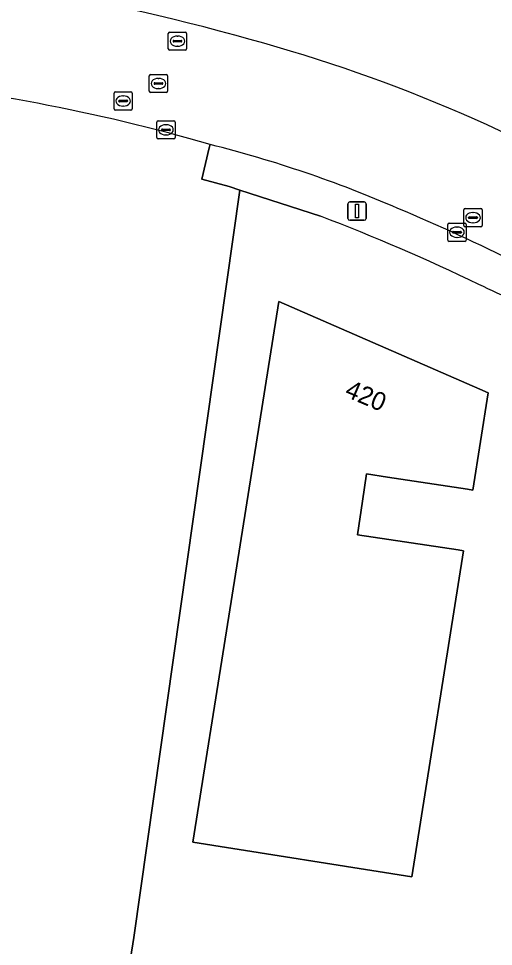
# Model space of a CAD drawing. Extents: x 154324 to 155744, y 382937 to 384188.
# Drawn here: x 155321.8 to 155347.8, y 383421.7 to 383472.5 of the extents above; entities that cross this region are included whole.
import ezdxf

# ---------------------------------------------------------------- set-up
doc = ezdxf.new("R2010")
doc.units = 0
for name, color, linetype in [('IMGEO_Erf', 7, 'Continuous'), ('IMGEO_Groenvoorziening', 7, 'Continuous'), ('IMGEO_Kolk', 7, 'Continuous'), ('IMGEO_Lichtmast', 7, 'Continuous'), ('IMGEO_Pand', 7, 'Continuous'), ('IMGEO_Pand_nummerreeks', 7, 'Continuous'), ('IMGEO_Rijbaan_lokaal_open', 7, 'Continuous'), ('IMGEO_Rioolput', 7, 'Continuous'), ('IMGEO_Voetpad_open', 7, 'Continuous')]:
    doc.layers.add(name, color=color, linetype=linetype)

msp = doc.modelspace()

# ---------------------------------------------------------------- linework, layer by layer
at = {"layer": 'IMGEO_Erf'}
msp.add_lwpolyline([(155338.312, 383461.713), (155333.894, 383463.145), (155328.096, 383422.22), (155326.654, 383413.134), (155323.037, 383390.342), (155343.85, 383387.039), (155363.801, 383383.796)], dxfattribs=at)
msp.add_lwpolyline([(155343.315, 383425.544), (155331.323, 383427.445), (155333.164, 383439.018), (155336.033, 383457.049), (155347.048, 383452.243), (155347.501, 383452.045), (155346.667, 383446.721), (155346.37, 383446.766), (155341.993, 383447.428), (155340.844, 383447.602), (155340.619, 383446.119), (155340.34, 383444.275), (155345.852, 383443.441), (155346.148, 383443.396)], close=True, dxfattribs=at)
for centre, radius, start, end in [((155299.548, 383359.815), 109.022, 64.20617, 69.17205), ((155325.371, 383410.082), 52.545, 60.8513, 65.7078)]:
    msp.add_arc(centre, radius, start, end, dxfattribs=at)
at = {"layer": 'IMGEO_Groenvoorziening'}
for points in [[(155333.894, 383463.145), (155333.316, 383463.332), (155331.811, 383463.731), (155332.222, 383465.445), (155332.268, 383465.636)], [(155241.462, 383401.286), (155286.115, 383394.2), (155322.727, 383388.39), (155323.037, 383390.342), (155326.654, 383413.134), (155328.096, 383422.22), (155333.894, 383463.145)]]:
    msp.add_lwpolyline(points, dxfattribs=at)
for centre, radius, start, end in [((155304.555, 383366.626), 108.94, 74.06499, 88.76862), ((155312.033, 383388.632), 85.735, 58.41362, 74.83277), ((155304.104, 383368.576), 101.064, 73.81877, 84.84587)]:
    msp.add_arc(centre, radius, start, end, dxfattribs=at)
at = {"layer": 'IMGEO_Kolk'}
for p, q in [((155329.353, 383466.014), (155329.353, 383466.866)), ((155329.428, 383466.94), (155330.28, 383466.94)), ((155330.354, 383466.866), (155330.354, 383466.014)), ((155329.612, 383466.434), (155329.612, 383466.446)), ((155330.05, 383466.397), (155329.652, 383466.397)), ((155329.655, 383466.483), (155330.053, 383466.483)), ((155329.841, 383466.72), (155329.866, 383466.72)), ((155330.096, 383466.446), (155330.096, 383466.434)), ((155330.28, 383465.94), (155329.428, 383465.94)), ((155329.864, 383466.16), (155329.839, 383466.16)), ((155345.293, 383460.408), (155345.293, 383461.26)), ((155345.368, 383461.334), (155346.22, 383461.334)), ((155346.294, 383461.26), (155346.294, 383460.408)), ((155345.552, 383460.828), (155345.552, 383460.84)), ((155345.99, 383460.791), (155345.592, 383460.791)), ((155345.595, 383460.877), (155345.993, 383460.877)), ((155345.781, 383461.114), (155345.806, 383461.114)), ((155346.036, 383460.84), (155346.036, 383460.828)), ((155346.22, 383460.334), (155345.368, 383460.334)), ((155345.804, 383460.554), (155345.779, 383460.554))]:
    msp.add_line(p, q, dxfattribs=at)
for points in [[(155329.353, 383466.014), (155329.353, 383466.866)], [(155329.428, 383466.94), (155330.28, 383466.94)], [(155330.354, 383466.866), (155330.354, 383466.014)], [(155330.28, 383465.94), (155329.428, 383465.94)], [(155345.293, 383460.408), (155345.293, 383461.26)], [(155345.368, 383461.334), (155346.22, 383461.334)], [(155346.294, 383461.26), (155346.294, 383460.408)], [(155346.22, 383460.334), (155345.368, 383460.334)]]:
    msp.add_lwpolyline(points, dxfattribs=at)
for centre, radius, start, end in [((155329.43, 383466.864), 0.0765, 91.552, 178.448), ((155329.43, 383466.864), 0.0765, 91.552, 178.448), ((155330.278, 383466.864), 0.0765, 1.552, 88.448), ((155330.278, 383466.864), 0.0765, 1.552, 88.448), ((155329.652, 383466.443), 0.0403, 85.8775, 175.7526), ((155329.649, 383466.433), 0.0366, 178.938, 274.7102), ((155330.053, 383466.44), 0.043, 264.8664, 352.4533), ((155330.057, 383466.445), 0.0386, 1.7309, 96.639), ((155329.43, 383466.016), 0.0765, 181.552, 268.448), ((155329.43, 383466.016), 0.0765, 181.552, 268.448), ((155330.278, 383466.016), 0.0765, 271.552, 358.448), ((155330.278, 383466.016), 0.0765, 271.552, 358.448), ((155345.37, 383461.258), 0.0765, 91.552, 178.448), ((155345.37, 383461.258), 0.0765, 91.552, 178.448), ((155346.218, 383461.258), 0.0765, 1.552, 88.448), ((155346.218, 383461.258), 0.0765, 1.552, 88.448), ((155345.592, 383460.837), 0.0403, 85.8775, 175.7526), ((155345.589, 383460.827), 0.0366, 178.938, 274.7102), ((155345.993, 383460.834), 0.043, 264.8664, 352.4533), ((155345.997, 383460.839), 0.0386, 1.7309, 96.639), ((155345.37, 383460.41), 0.0765, 181.552, 268.448), ((155345.37, 383460.41), 0.0765, 181.552, 268.448), ((155346.218, 383460.41), 0.0765, 271.552, 358.448), ((155346.218, 383460.41), 0.0765, 271.552, 358.448)]:
    msp.add_arc(centre, radius, start, end, dxfattribs=at)
for centre, major_axis, ratio, start_param, end_param in [((155329.84, 383466.44), (-0.387, 0.002), 0.722429, 4.712389, 7.853982), ((155329.865, 383466.44), (-0.39, 0.002), 0.717154, 1.570796, 4.712389), ((155345.78, 383460.834), (-0.387, 0.002), 0.722429, 4.712389, 7.853982), ((155345.805, 383460.834), (-0.39, 0.002), 0.717154, 1.570796, 4.712389)]:
    msp.add_ellipse(centre, major_axis=major_axis, ratio=ratio, start_param=start_param, end_param=end_param, dxfattribs=at)
at = {"layer": 'IMGEO_Lichtmast'}
for p, q in [((155339.824, 383461.59), (155339.824, 383462.39)), ((155339.824, 383462.39), (155339.824, 383461.59)), ((155339.924, 383462.49), (155340.714, 383462.49)), ((155340.714, 383462.49), (155339.924, 383462.49)), ((155340.814, 383462.39), (155340.814, 383461.59)), ((155340.814, 383461.59), (155340.814, 383462.39)), ((155340.714, 383461.49), (155339.924, 383461.49)), ((155339.924, 383461.49), (155340.714, 383461.49))]:
    msp.add_line(p, q, dxfattribs=at)
msp.add_lwpolyline([(155340.244, 383462.365), (155340.394, 383462.365), (155340.394, 383461.615), (155340.244, 383461.615), (155340.244, 383462.365)], dxfattribs=at)
for centre, start, end in [((155339.924, 383462.39), 90, 180), ((155339.924, 383462.39), 90, 180), ((155340.714, 383462.39), 0, 90), ((155340.714, 383462.39), 360, 90), ((155339.924, 383461.59), 180, 270), ((155339.924, 383461.59), 180, 270), ((155340.714, 383461.59), 270, 0), ((155340.714, 383461.59), 270, 0)]:
    msp.add_arc(centre, 0.1, start, end, dxfattribs=at)
at = {"layer": 'IMGEO_Pand'}
msp.add_lwpolyline([(155341.993, 383447.428), (155346.37, 383446.766), (155346.667, 383446.721), (155347.501, 383452.045), (155347.048, 383452.243), (155336.033, 383457.049), (155333.164, 383439.018), (155331.323, 383427.445), (155343.315, 383425.544), (155346.148, 383443.396), (155345.852, 383443.441), (155340.34, 383444.275), (155340.619, 383446.119), (155340.844, 383447.602)], close=True, dxfattribs=at)
at = {"layer": 'IMGEO_Rijbaan_lokaal_open'}
for centre, radius, start, end in [((155304.555, 383366.626), 108.94, 74.06499, 88.76862), ((155312.033, 383388.632), 85.735, 58.41362, 74.83277), ((155304.104, 383368.576), 101.064, 73.81877, 84.84587), ((155315.957, 383400.762), 66.893, 66.57551, 75.8872), ((155302.55, 383366.417), 103.746, 63.30392, 67.32185)]:
    msp.add_arc(centre, radius, start, end, dxfattribs=at)
at = {"layer": 'IMGEO_Rioolput'}
for p, q in [((155329.982, 383470.866), (155329.982, 383471.718)), ((155330.057, 383471.792), (155330.909, 383471.792)), ((155330.284, 383471.335), (155330.682, 383471.335)), ((155330.47, 383471.572), (155330.495, 383471.572)), ((155330.983, 383471.718), (155330.983, 383470.866)), ((155330.241, 383471.286), (155330.241, 383471.298)), ((155330.679, 383471.249), (155330.281, 383471.249)), ((155330.493, 383471.012), (155330.468, 383471.012)), ((155330.725, 383471.298), (155330.725, 383471.286)), ((155330.909, 383470.792), (155330.057, 383470.792)), ((155328.941, 383468.55), (155328.941, 383469.402)), ((155329.016, 383469.476), (155329.868, 383469.476)), ((155329.942, 383469.402), (155329.942, 383468.55)), ((155329.2, 383468.97), (155329.2, 383468.982)), ((155329.638, 383468.933), (155329.24, 383468.933)), ((155329.243, 383469.019), (155329.641, 383469.019)), ((155329.429, 383469.256), (155329.454, 383469.256)), ((155329.684, 383468.982), (155329.684, 383468.97)), ((155327.009, 383467.592), (155327.009, 383468.444)), ((155327.084, 383468.518), (155327.936, 383468.518)), ((155327.497, 383468.298), (155327.522, 383468.298)), ((155328.01, 383468.444), (155328.01, 383467.592)), ((155329.868, 383468.476), (155329.016, 383468.476)), ((155329.452, 383468.696), (155329.427, 383468.696)), ((155327.268, 383468.012), (155327.268, 383468.024)), ((155327.706, 383467.975), (155327.308, 383467.975)), ((155327.311, 383468.061), (155327.709, 383468.061)), ((155327.752, 383468.024), (155327.752, 383468.012)), ((155327.936, 383467.518), (155327.084, 383467.518)), ((155327.52, 383467.738), (155327.495, 383467.738)), ((155346.172, 383461.207), (155346.172, 383462.059)), ((155346.247, 383462.133), (155347.099, 383462.133)), ((155346.66, 383461.913), (155346.685, 383461.913)), ((155347.173, 383462.059), (155347.173, 383461.207)), ((155346.431, 383461.627), (155346.431, 383461.639)), ((155346.869, 383461.59), (155346.471, 383461.59)), ((155346.474, 383461.676), (155346.872, 383461.676)), ((155346.683, 383461.353), (155346.658, 383461.353)), ((155346.915, 383461.639), (155346.915, 383461.627)), ((155347.099, 383461.133), (155346.247, 383461.133))]:
    msp.add_line(p, q, dxfattribs=at)
for points in [[(155329.982, 383470.866), (155329.982, 383471.718)], [(155330.057, 383471.792), (155330.909, 383471.792)], [(155330.983, 383471.718), (155330.983, 383470.866)], [(155330.909, 383470.792), (155330.057, 383470.792)], [(155328.941, 383468.55), (155328.941, 383469.402)], [(155329.016, 383469.476), (155329.868, 383469.476)], [(155329.942, 383469.402), (155329.942, 383468.55)], [(155327.009, 383467.592), (155327.009, 383468.444)], [(155327.084, 383468.518), (155327.936, 383468.518)], [(155328.01, 383468.444), (155328.01, 383467.592)], [(155329.868, 383468.476), (155329.016, 383468.476)], [(155327.936, 383467.518), (155327.084, 383467.518)], [(155346.172, 383461.207), (155346.172, 383462.059)], [(155346.247, 383462.133), (155347.099, 383462.133)], [(155347.173, 383462.059), (155347.173, 383461.207)], [(155347.099, 383461.133), (155346.247, 383461.133)]]:
    msp.add_lwpolyline(points, dxfattribs=at)
for centre, radius, start, end in [((155330.059, 383471.716), 0.0765, 91.552, 178.448), ((155330.059, 383471.716), 0.0765, 91.552, 178.448), ((155330.281, 383471.295), 0.0403, 85.8775, 175.7526), ((155330.686, 383471.297), 0.0386, 1.7309, 96.639), ((155330.907, 383471.716), 0.0765, 1.552, 88.448), ((155330.907, 383471.716), 0.0765, 1.552, 88.448), ((155330.059, 383470.868), 0.0765, 181.552, 268.448), ((155330.059, 383470.868), 0.0765, 181.552, 268.448), ((155330.278, 383471.285), 0.0366, 178.938, 274.7102), ((155330.682, 383471.292), 0.043, 264.8664, 352.4533), ((155330.907, 383470.868), 0.0765, 271.552, 358.448), ((155330.907, 383470.868), 0.0765, 271.552, 358.448), ((155329.018, 383469.4), 0.0765, 91.552, 178.448), ((155329.018, 383469.4), 0.0765, 91.552, 178.448), ((155329.866, 383469.4), 0.0765, 1.552, 88.448), ((155329.866, 383469.4), 0.0765, 1.552, 88.448), ((155329.24, 383468.979), 0.0403, 85.8775, 175.7526), ((155329.237, 383468.969), 0.0366, 178.938, 274.7102), ((155329.641, 383468.976), 0.043, 264.8664, 352.4533), ((155329.645, 383468.981), 0.0386, 1.7309, 96.639), ((155327.086, 383468.442), 0.0765, 91.552, 178.448), ((155327.086, 383468.442), 0.0765, 91.552, 178.448), ((155327.934, 383468.442), 0.0765, 1.552, 88.448), ((155327.934, 383468.442), 0.0765, 1.552, 88.448), ((155329.018, 383468.552), 0.0765, 181.552, 268.448), ((155329.018, 383468.552), 0.0765, 181.552, 268.448), ((155329.866, 383468.552), 0.0765, 271.552, 358.448), ((155329.866, 383468.552), 0.0765, 271.552, 358.448), ((155327.308, 383468.021), 0.0403, 85.8775, 175.7526), ((155327.305, 383468.011), 0.0366, 178.938, 274.7102), ((155327.709, 383468.018), 0.043, 264.8664, 352.4533), ((155327.713, 383468.023), 0.0386, 1.7309, 96.639), ((155327.086, 383467.594), 0.0765, 181.552, 268.448), ((155327.086, 383467.594), 0.0765, 181.552, 268.448), ((155327.934, 383467.594), 0.0765, 271.552, 358.448), ((155327.934, 383467.594), 0.0765, 271.552, 358.448), ((155346.249, 383462.057), 0.0765, 91.552, 178.448), ((155346.249, 383462.057), 0.0765, 91.552, 178.448), ((155347.097, 383462.057), 0.0765, 1.552, 88.448), ((155347.097, 383462.057), 0.0765, 1.552, 88.448), ((155346.249, 383461.209), 0.0765, 181.552, 268.448), ((155346.249, 383461.209), 0.0765, 181.552, 268.448), ((155346.471, 383461.636), 0.0403, 85.8775, 175.7526), ((155346.468, 383461.626), 0.0366, 178.938, 274.7102), ((155346.872, 383461.633), 0.043, 264.8664, 352.4533), ((155346.876, 383461.638), 0.0386, 1.7309, 96.639), ((155347.097, 383461.209), 0.0765, 271.552, 358.448), ((155347.097, 383461.209), 0.0765, 271.552, 358.448)]:
    msp.add_arc(centre, radius, start, end, dxfattribs=at)
for centre, major_axis, ratio, start_param, end_param in [((155330.469, 383471.292), (-0.387, 0.002), 0.722429, 4.712389, 7.853982), ((155330.494, 383471.292), (-0.39, 0.002), 0.717154, 1.570796, 4.712389), ((155329.428, 383468.976), (-0.387, 0.002), 0.722429, 4.712389, 7.853982), ((155329.453, 383468.976), (-0.39, 0.002), 0.717154, 1.570796, 4.712389), ((155327.496, 383468.018), (-0.387, 0.002), 0.722429, 4.712389, 7.853982), ((155327.521, 383468.018), (-0.39, 0.002), 0.717154, 1.570796, 4.712389), ((155346.659, 383461.633), (-0.387, 0.002), 0.722429, 4.712389, 7.853982), ((155346.684, 383461.633), (-0.39, 0.002), 0.717154, 1.570796, 4.712389)]:
    msp.add_ellipse(centre, major_axis=major_axis, ratio=ratio, start_param=start_param, end_param=end_param, dxfattribs=at)
at = {"layer": 'IMGEO_Voetpad_open'}
msp.add_lwpolyline([(155332.268, 383465.636), (155332.222, 383465.445), (155331.811, 383463.731), (155333.316, 383463.332), (155333.894, 383463.145), (155338.312, 383461.713)], dxfattribs=at)
for centre, radius, start, end in [((155315.957, 383400.762), 66.893, 66.57551, 75.8872), ((155299.548, 383359.815), 109.022, 64.20617, 69.17205), ((155302.55, 383366.417), 103.746, 63.30392, 67.32185), ((155325.371, 383410.082), 52.545, 60.8513, 65.7078)]:
    msp.add_arc(centre, radius, start, end, dxfattribs=at)

# ---------------------------------------------------------------- texts
at = {"layer": 'IMGEO_Pand_nummerreeks'}
msp.add_text('420', height=1, rotation=336.9232, dxfattribs=at).set_placement((155339.593, 383451.868))

doc.saveas('drawing.dxf')
